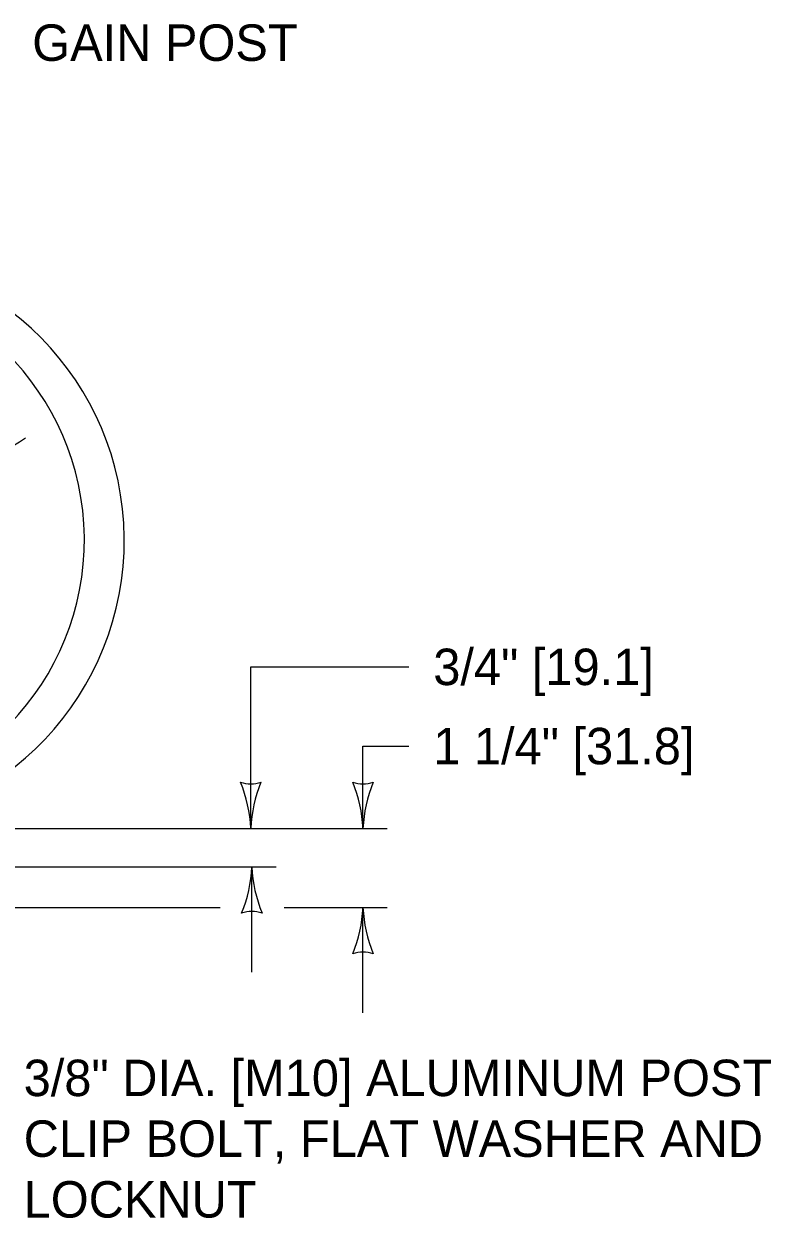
# Model space of a CAD drawing. Extents: x 49991.4 to 50021, y 49987.6 to 50011.4.
# Drawn here: x 50011.541 to 50012.771, y 49995.573 to 49997.539 of the extents above; entities that cross this region are included whole.
import ezdxf

# ---------------------------------------------------------------- set-up
doc = ezdxf.new("R2010")
doc.units = 0
for name, color, linetype in [('Level 1', 7, 'Continuous'), ('Level 2', 7, 'Continuous'), ('Level 3', 7, 'Continuous')]:
    doc.layers.add(name, color=color, linetype=linetype)

msp = doc.modelspace()

# ---------------------------------------------------------------- linework, layer by layer
at = {"layer": 'Level 1'}
for centre, radius, start, end in [((50011.2318, 49996.6881), 0.4748, 272.4284, 88.6971), ((50011.2063, 49996.6888), 0.4346, 271.24, 90)]:
    msp.add_arc(centre, radius, start, end, dxfattribs=at)
msp.add_spline([(50011.3236, 49996.7569), (50011.338, 49996.7638), (50011.389, 49996.7705), (50011.4178, 49996.8082), (50011.46, 49996.8281), (50011.5021, 49996.8348), (50011.5442, 49996.857)], degree=3, dxfattribs=at)
at = {"layer": 'Level 3'}
for p, q in [((50011.9149, 49996.2141), (50011.9149, 49996.4801)), ((50011.9149, 49996.4801), (50012.1753, 49996.4801)), ((50012.0996, 49996.2141), (50012.0996, 49996.3497)), ((50012.0996, 49996.3497), (50012.1753, 49996.3497)), ((50011.3519, 49996.2141), (50012.1396, 49996.2141)), ((50011.1981, 49996.1507), (50011.9566, 49996.1507)), ((50011.9166, 49995.9773), (50011.9166, 49996.1507)), ((50011.0152, 49996.0839), (50011.8645, 49996.0839)), ((50011.9699, 49996.0839), (50012.1396, 49996.0839)), ((50012.0996, 49995.9105), (50012.0996, 49996.0839))]:
    msp.add_line(p, q, dxfattribs=at)
for centre, radius, start, end in [((50011.9149, 49996.3423), 0.0548, 252.1388, 287.8612), ((50011.6822, 49996.2026), 0.233, 2.8273, 22.0772), ((50012.137, 49996.2049), 0.2223, 157.456, 177.6395), ((50012.0996, 49996.3423), 0.0548, 252.1388, 287.8612), ((50011.8669, 49996.2026), 0.233, 2.8273, 22.0772), ((50012.3217, 49996.2049), 0.2223, 157.456, 177.6395), ((50011.6945, 49996.1599), 0.2223, 337.456, 357.6395), ((50012.1493, 49996.1622), 0.233, 182.8273, 202.0772), ((50011.8775, 49996.0931), 0.2223, 337.456, 357.6395), ((50012.3323, 49996.0954), 0.233, 182.8273, 202.0772), ((50011.9166, 49996.0225), 0.0548, 72.1388, 107.8612), ((50012.0996, 49995.9557), 0.0548, 72.1388, 107.8612)]:
    msp.add_arc(centre, radius, start, end, dxfattribs=at)

# ---------------------------------------------------------------- texts
at = {"layer": 'Level 2'}
for s, p in [('GAIN POST', (50011.5551, 49997.4778)), ('3/4" [19.1]', (50012.2153, 49996.4501)), ('1 1/4" [31.8]', (50012.2153, 49996.3197)), ('3/8" DIA. [M10] ALUMINUM POST ', (50011.541, 49995.7734)), ('CLIP BOLT, FLAT WASHER AND ', (50011.541, 49995.6734)), ('LOCKNUT', (50011.541, 49995.5734))]:
    msp.add_text(s, height=0.06, dxfattribs=at).set_placement(p)

doc.saveas('drawing.dxf')
